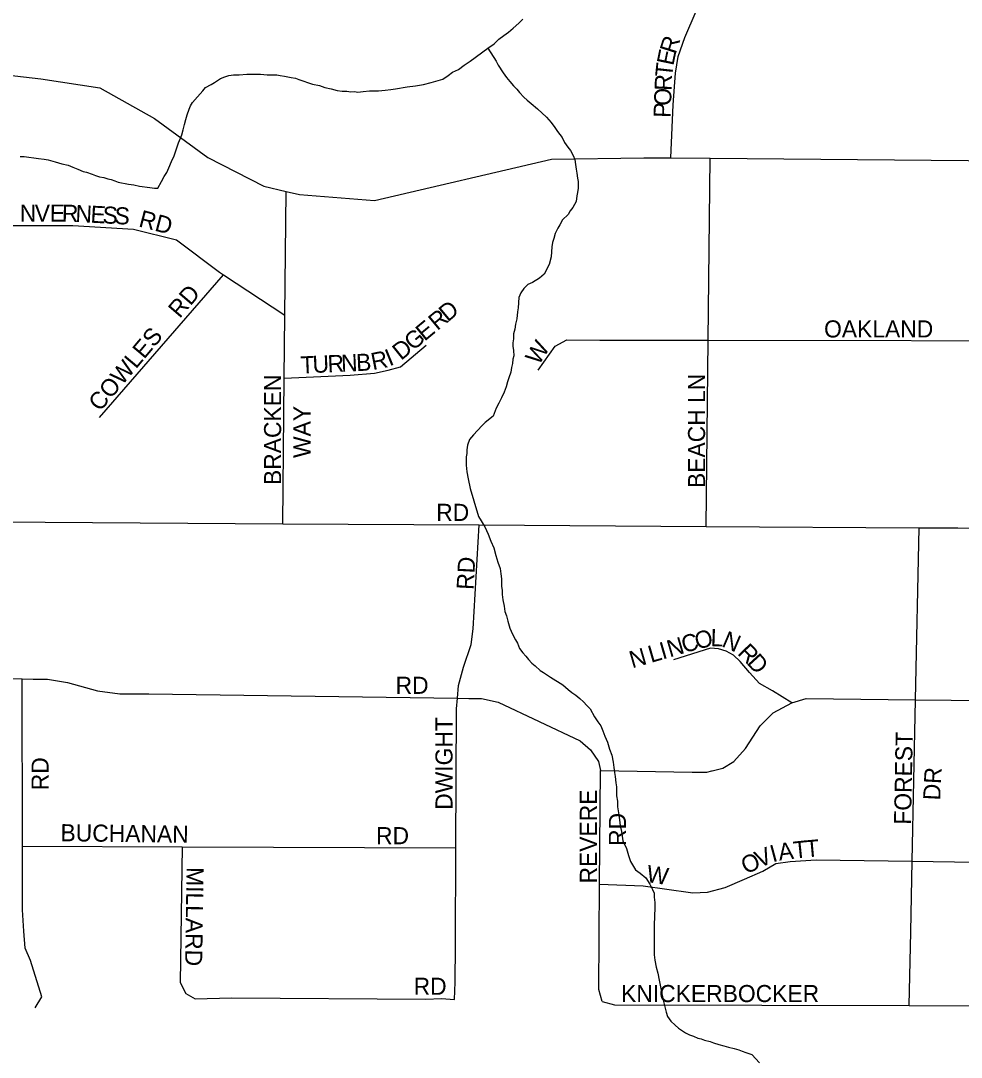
# Model space of a CAD drawing. Extents: x 2010165 to 2382125, y 1060529 to 1407316.
# Drawn here: x 2120912 to 2123664, y 1267507 to 1270540 of the extents above; entities that cross this region are included whole.
import ezdxf

# ---------------------------------------------------------------- set-up
doc = ezdxf.new("R2010")
doc.units = 0
for name, color, linetype in [('GM_X_City_Street', 7, 'Continuous'), ('GM_X_City_Street_Text', 7, 'Continuous'), ('GM_X_Minor_River', 7, 'Continuous')]:
    doc.layers.add(name, color=color, linetype=linetype)

msp = doc.modelspace()

# ---------------------------------------------------------------- linework, layer by layer
at = {"layer": 'GM_X_City_Street'}
for points in [[(2122814.6, 1270138.1), (2122820.9, 1270294), (2122828, 1270386.4), (2122835.6, 1270434.7), (2122855.1, 1270491), (2122888.4, 1270567.6), (2122896.4, 1270585.6)], [(2120792, 1270390.5), (2120970.6, 1270369.4), (2121142.7, 1270343.6), (2121302.8, 1270253.5), (2121459, 1270139.5), (2121623.1, 1270055.5), (2121688.4, 1270040.5), (2121727.2, 1270031.5), (2121947.3, 1270013.7), (2122465.3, 1270134.5), (2122735.5, 1270138.8), (2122814.6, 1270138.1), (2122929, 1270137.2), (2124116, 1270127.1), (2124592.4, 1270123.1), (2125050.4, 1270119.2), (2125261, 1270121.5), (2126064.8, 1270130.3)], [(2122918, 1269060), (2122923.5, 1269604.6), (2122929, 1270137.2)], [(2121678.3, 1269067.8), (2121682.7, 1269493.8), (2121684.6, 1269678.4), (2121688.4, 1270040.5)], [(2120885.5, 1269940.2), (2121063.6, 1269940.1), (2121241.7, 1269929.6), (2121367.3, 1269898.2), (2121493, 1269803.9), (2121504.7, 1269796.2), (2121684.6, 1269678.4)], [(2121142.3, 1269378.3), (2121504.7, 1269796.2)], [(2122425.6, 1269517.6), (2122476, 1269587.6), (2122510.1, 1269605.5), (2122606.2, 1269605.1), (2122923.5, 1269604.6), (2124112.6, 1269602.6), (2124193.7, 1269602.5), (2124576.9, 1269598.8)], [(2121682.7, 1269493.8), (2121875.3, 1269502.6), (2121946.7, 1269508.5), (2121986.7, 1269516.9), (2122022.7, 1269527.3), (2122098.2, 1269590.3)], [(2119222.9, 1269093.1), (2120523.7, 1269077), (2120842.1, 1269073.1), (2121678.3, 1269067.8), (2122253.4, 1269064.2), (2122918, 1269060), (2123540.6, 1269056.1), (2123654.7, 1269055.4), (2124109.1, 1269053.5), (2124157.2, 1269053.3), (2124271.3, 1269056.8), (2124558.8, 1269064.7), (2124589.6, 1269065.5), (2125090.2, 1269085.5), (2125220.4, 1269093), (2125228.4, 1269093), (2125340.5, 1269092.5), (2126423.4, 1269090.4)], [(2122181, 1267676.1), (2122183.2, 1267726.3), (2122183.7, 1267832.5), (2122185, 1268119.2), (2122186.9, 1268526.2), (2122189.8, 1268557.2), (2122193.2, 1268594.3), (2122207.4, 1268648.4), (2122229.8, 1268714.5), (2122236, 1268760.6), (2122253.4, 1269064.2)], [(2123516.6, 1267873.5), (2123520.8, 1268080.5), (2123530.4, 1268552.9), (2123540.6, 1269056.1)], [(2123167.9, 1268544.2), (2123112, 1268578.5), (2123074.1, 1268600.7), (2123044.2, 1268632.9), (2123017.4, 1268665), (2122997.4, 1268683.7), (2122976.4, 1268695.3), (2122954, 1268701.7), (2122930.4, 1268703.6), (2122822.1, 1268669.9)], [(2120669.8, 1268618.7), (2120916.1, 1268614.1), (2120948.1, 1268613.5), (2120990.1, 1268613.4), (2121048.1, 1268603.1), (2121136.1, 1268578.7), (2121201.7, 1268570), (2121286.2, 1268570), (2122189.8, 1268557.2), (2122222.9, 1268556.7), (2122260.4, 1268556.7), (2122309.1, 1268545.8), (2122548.8, 1268432.5), (2122578.7, 1268406.3), (2122602.6, 1268372.1), (2122608.5, 1268346), (2122876.7, 1268340.9), (2122919.2, 1268340.6), (2122933.8, 1268344.3)], [(2120953.7, 1267651.2), (2120973.8, 1267683.2), (2120940.3, 1267789.6), (2120924.4, 1267825.7), (2120920.7, 1267875.9), (2120917, 1267938), (2120916.7, 1268124.4), (2120916.1, 1268614.1)], [(2122933.8, 1268344.3), (2122935.1, 1268344.6), (2122966.8, 1268352.5), (2122999, 1268372.5), (2123033.2, 1268410.4), (2123075.5, 1268476.4), (2123113.7, 1268514.3), (2123167.9, 1268544.2), (2123210, 1268556), (2123530.4, 1268552.9), (2123946.7, 1268549), (2124014.7, 1268548.7), (2124102.8, 1268542.3), (2124477, 1268494.6), (2124515.6, 1268490.9), (2124521.7, 1268490.3)], [(2122613.4, 1267670.3), (2122603.5, 1267704.5), (2122605.9, 1268013.2), (2122608.5, 1268346)], [(2120916.7, 1268124.4), (2121384.2, 1268122.5), (2122185, 1268119.2)], [(2121384.2, 1268122.5), (2121378.4, 1267725.6), (2121394.3, 1267693.4), (2121422.3, 1267677.3), (2121528.4, 1267680.9), (2122096.9, 1267676.5), (2122143, 1267678.3), (2122181, 1267676.1)], [(2122871.5, 1267989.1), (2122879.1, 1267988), (2122921.1, 1267989.9), (2122973.2, 1268003.7), (2123029.4, 1268027.5), (2123083.6, 1268051.3), (2123121.7, 1268073.2), (2123163.8, 1268079.1), (2123239.9, 1268084.8), (2123520.8, 1268080.5), (2124508.7, 1268065.3)], [(2122605.9, 1268013.2), (2122733, 1268008.7), (2122871.5, 1267989.1)], [(2123512.2, 1267658.5), (2123516.6, 1267873.5), (2123516.6, 1267873.5)], [(2122613.4, 1267670.3), (2122649.4, 1267660.2), (2123512.2, 1267658.5), (2124503.2, 1267656.5), (2124717.3, 1267653.6), (2124791.4, 1267651.3), (2124881.4, 1267642.9), (2124967.5, 1267634.5), (2125023.5, 1267632.3), (2125113.6, 1267631.9), (2125178.8, 1267632.5)]]:
    msp.add_lwpolyline(points, dxfattribs=at)
at = {"layer": 'GM_X_Minor_River'}
for points in [[(2122008.4, 1270340.6), (2122020.5, 1270342.6), (2122030.5, 1270344.7), (2122042.5, 1270346.7), (2122066.6, 1270348.8), (2122090.7, 1270352.9), (2122112.7, 1270359), (2122132.8, 1270365.1), (2122146.8, 1270369.1), (2122162.8, 1270379.2), (2122174.8, 1270389.3), (2122192.9, 1270397.3), (2122208.9, 1270409.4), (2122226.9, 1270421.5), (2122278.9, 1270459.8), (2122297, 1270471.9), (2122311, 1270486), (2122325, 1270496.1), (2122339, 1270506.1), (2122353, 1270518.2), (2122369, 1270532.3), (2122381, 1270544.4)], [(2122278.3, 1270459.3), (2122303.1, 1270421.8), (2122309.2, 1270409.8), (2122323.3, 1270387.7), (2122333.4, 1270373.7), (2122343.5, 1270361.7), (2122353.6, 1270349.7), (2122363.6, 1270339.7), (2122371.7, 1270329.7), (2122383.8, 1270315.7), (2122393.8, 1270307.7), (2122405.9, 1270297.7), (2122424, 1270281.7), (2122450.2, 1270257.7), (2122464.3, 1270241.7), (2122474.4, 1270227.7), (2122482.5, 1270215.7), (2122496.6, 1270197.6), (2122502.6, 1270183.6), (2122512.7, 1270169.6), (2122520.8, 1270159.6), (2122528.8, 1270145.6), (2122532.9, 1270133.6), (2122535, 1270119.5), (2122537, 1270105.5), (2122539.1, 1270093.4), (2122541.1, 1270079.4), (2122543.2, 1270069.4), (2122543.2, 1270049.3), (2122541.3, 1270037.3), (2122539.3, 1270027.2), (2122537.3, 1270011.2), (2122527.4, 1269993.1), (2122519.4, 1269983), (2122513.4, 1269973), (2122497.4, 1269956.9), (2122489.4, 1269942.8), (2122483.4, 1269932.7), (2122475.5, 1269916.7), (2122471.5, 1269902.6), (2122467.5, 1269890.6), (2122465.6, 1269878.5), (2122463.7, 1269848.4), (2122457.7, 1269826.3), (2122443.8, 1269798.2), (2122429.8, 1269786.1), (2122409.7, 1269774), (2122395.7, 1269767.9), (2122383.7, 1269755.8), (2122375.7, 1269743.8), (2122369.8, 1269729.7), (2122367.9, 1269699.6), (2122365.9, 1269687.6), (2122364, 1269667.5), (2122360, 1269651.4), (2122358, 1269637.4), (2122354.1, 1269623.3), (2122354.1, 1269609.3), (2122352.1, 1269597.2), (2122352.2, 1269587.2), (2122354.2, 1269575.2), (2122354.3, 1269559.1), (2122352.3, 1269549.1), (2122350.4, 1269537), (2122348.4, 1269525), (2122346.4, 1269510.9), (2122340.5, 1269494.8), (2122336.5, 1269482.8), (2122332.5, 1269468.7), (2122326.6, 1269452.7), (2122318.6, 1269436.6), (2122310.6, 1269420.5), (2122302.6, 1269406.4), (2122294.7, 1269382.3), (2122270.7, 1269364.2), (2122260.7, 1269354.1), (2122236.7, 1269328), (2122224.7, 1269313.9), (2122218.7, 1269297.8), (2122216.8, 1269283.8), (2122216.8, 1269273.7), (2122214.8, 1269263.7), (2122214.9, 1269253.7), (2122214.9, 1269239.6), (2122217, 1269219.6), (2122221.1, 1269199.5), (2122227.2, 1269171.4), (2122237.4, 1269135.3), (2122251.6, 1269089.2), (2122269.7, 1269059.2), (2122279.8, 1269037.2), (2122287.9, 1269017.1), (2122296, 1268997.1), (2122302.1, 1268975), (2122308.2, 1268955), (2122314.3, 1268936.9), (2122316.4, 1268920.9), (2122318.4, 1268906.9), (2122318.5, 1268894.8)], [(2120909.5, 1270142.5), (2120921.5, 1270142.5), (2120935.6, 1270140.6), (2120949.6, 1270138.6), (2120963.7, 1270136.6), (2120979.7, 1270134.7), (2120991.8, 1270132.7), (2121011.9, 1270126.7), (2121032, 1270120.8), (2121050, 1270116.8), (2121064.1, 1270110.9), (2121078.2, 1270104.9), (2121094.2, 1270098.9), (2121104.3, 1270096.9), (2121120.4, 1270091), (2121130.4, 1270087), (2121142.5, 1270083), (2121154.5, 1270081), (2121166.6, 1270077.1), (2121176.6, 1270075.1), (2121186.6, 1270071.1), (2121196.7, 1270067.1), (2121226.8, 1270061.2), (2121242.9, 1270059.3), (2121258.9, 1270055.3), (2121289.1, 1270051.4), (2121303.1, 1270049.4), (2121313.1, 1270049.4), (2121323.1, 1270069.5), (2121331.1, 1270083.6), (2121339.1, 1270095.7), (2121345, 1270109.7), (2121353, 1270127.8), (2121361, 1270143.9), (2121366.9, 1270162), (2121372.9, 1270182.1), (2121378.9, 1270196.1), (2121382.8, 1270206.2), (2121386.8, 1270220.2), (2121390.7, 1270236.3), (2121394.7, 1270250.4), (2121398.7, 1270264.4), (2121404.6, 1270280.5), (2121408.6, 1270290.5), (2121414.6, 1270300.6), (2121428.6, 1270316.7), (2121444.6, 1270334.8), (2121452.6, 1270344.8), (2121468.6, 1270352.9), (2121478.6, 1270359), (2121496.6, 1270371.1), (2121508.7, 1270375.1), (2121520.7, 1270379.2), (2121534.7, 1270381.2), (2121550.8, 1270381.3), (2121572.9, 1270383.3), (2121594.9, 1270383.4), (2121613, 1270383.5), (2121633.1, 1270381.5), (2121649.1, 1270381.6), (2121661.2, 1270381.6), (2121671.2, 1270379.6), (2121683.2, 1270377.7), (2121693.3, 1270375.7), (2121703.3, 1270373.7), (2121715.4, 1270371.8), (2121725.4, 1270367.8), (2121765.6, 1270353.9), (2121785.7, 1270349.9), (2121801.8, 1270343.9), (2121819.8, 1270340), (2121837.9, 1270336), (2121852, 1270334.1), (2121866, 1270334.1), (2121878, 1270332.1), (2121888.1, 1270332.2), (2121898.1, 1270330.2), (2121914.2, 1270332.2), (2121932.2, 1270334.3), (2121958.3, 1270334.4), (2121978.4, 1270336.5), (2121994.4, 1270338.5), (2122008.4, 1270340.6)], [(2122318.5, 1268894.8), (2122318.5, 1268884.8), (2122320.5, 1268872.8), (2122320.6, 1268860.7), (2122322.6, 1268844.7), (2122326.7, 1268826.6), (2122328.8, 1268810.6), (2122332.8, 1268798.6), (2122336.9, 1268782.5), (2122343, 1268762.5), (2122351.1, 1268744.4), (2122359.2, 1268728.4), (2122365.2, 1268718.4), (2122371.3, 1268702.4), (2122381.4, 1268690.3), (2122389.4, 1268680.3), (2122397.5, 1268670.3), (2122407.6, 1268660.3), (2122417.6, 1268652.3), (2122431.7, 1268638.3), (2122441.8, 1268632.3), (2122461.9, 1268618.4), (2122498.1, 1268596.4), (2122514.2, 1268582.4), (2122524.2, 1268574.4), (2122536.3, 1268566.4), (2122548.4, 1268556.4), (2122558.5, 1268546.4), (2122568.5, 1268536.4), (2122578.6, 1268526.4), (2122590.7, 1268502.4), (2122600.8, 1268488.4), (2122608.9, 1268476.4), (2122614.9, 1268462.3), (2122621, 1268446.3), (2122629.1, 1268428.3), (2122635.2, 1268408.2), (2122641.3, 1268390.2), (2122645.4, 1268370.1), (2122647.4, 1268354.1), (2122649.5, 1268340), (2122651.5, 1268328), (2122653.6, 1268310), (2122655.6, 1268297.9), (2122655.7, 1268285.9), (2122655.7, 1268271.8), (2122657.8, 1268255.8), (2122657.8, 1268239.7), (2122659.9, 1268227.7), (2122661.9, 1268215.7), (2122664, 1268201.6), (2122666.1, 1268183.6), (2122670.1, 1268167.5), (2122674.2, 1268139.5), (2122684.4, 1268117.4), (2122690.4, 1268097.4), (2122696.5, 1268079.3), (2122704.6, 1268065.3), (2122710.7, 1268055.3), (2122724.7, 1268045.3), (2122740.8, 1268031.3), (2122752.9, 1268013.3), (2122761, 1267997.3), (2122765.1, 1267987.2), (2122765.1, 1267975.2), (2122767.2, 1267959.2), (2122767.2, 1267945.1), (2122765.4, 1267892.9), (2122765.5, 1267874.9), (2122765.5, 1267852.8), (2122765.6, 1267830.7), (2122765.7, 1267806.7), (2122767.8, 1267790.6), (2122771.8, 1267770.6), (2122775.9, 1267752.5), (2122780, 1267732.5), (2122784.1, 1267712.4), (2122788.2, 1267692.4), (2122792.3, 1267670.3), (2122796.3, 1267654.2), (2122800.4, 1267638.2), (2122804.4, 1267626.2), (2122814.5, 1267612.2), (2122826.6, 1267600.2), (2122836.7, 1267592.2), (2122856.8, 1267578.2), (2122868.8, 1267572.2), (2122880.9, 1267568.2), (2122893, 1267562.3), (2122903, 1267560.3), (2122913, 1267556.3), (2122929.1, 1267552.3), (2122939.2, 1267548.4), (2122955.2, 1267544.4), (2122969.3, 1267540.4), (2122983.3, 1267536.5), (2122999.4, 1267532.5), (2123013.5, 1267528.5), (2123023.5, 1267524.5), (2123033.6, 1267520.6), (2123051.7, 1267514.6)], [(2123051.7, 1267514.6), (2123073.8, 1267490.6)]]:
    msp.add_lwpolyline(points, dxfattribs=at)

# ---------------------------------------------------------------- texts
at = {"layer": 'GM_X_City_Street_Text'}
for s, rotation, p in [('R', 72.4098, (2122828.2, 1270439.7)), ('E', 78.2963, (2122821.4, 1270406.5)), ('T', 83.8272, (2122817.8, 1270372.8)), ('R', 87.8021, (2122816.4, 1270334.1)), ('O', 87.8085, (2122814.7, 1270290.1)), ('P', 87.8142, (2122813.3, 1270255)), ('N', 359.9758, (2120908.7, 1269951.7)), ('V', 359.9758, (2120952.7, 1269951.7)), ('E', 359.9727, (2120996.7, 1269951.7)), ('R', 359.1014, (2121031.7, 1269951.6)), ('N', 357.2233, (2121070.9, 1269951)), ('E', 356.8838, (2121114.8, 1269948.9)), ('S', 356.9172, (2121150, 1269947)), ('S', 356.9111, (2121185.1, 1269945.1)), ('RD', 345.2542, (2121254.3, 1269938.2)), ('RD', 49.4006, (2121376.8, 1269666.8)), ('R', 39.6684, (2122130.8, 1269631.2)), ('D', 39.6792, (2122161.3, 1269656.5)), ('E', 39.6709, (2122093.6, 1269600.3)), ('OAKLAND', 0, (2123262.7, 1269612.9)), ('COWLES', 49.9418, (2121143.5, 1269394)), ('G', 39.6792, (2122059.7, 1269572.3)), ('D', 38.6419, (2122024.6, 1269544.2)), ('W', 57.5237, (2122427.6, 1269529.3)), ('N', 2.4706, (2121850.1, 1269512.5)), ('B', 2.4694, (2121894.1, 1269514.4)), ('R', 11.4382, (2121942.1, 1269517.1)), ('I', 22.1643, (2121990.7, 1269527.9)), ('T', 2.4872, (2121731.4, 1269507.3)), ('U', 2.4706, (2121766.6, 1269508.9)), ('R', 2.4694, (2121810.5, 1269510.8)), ('BRACKEN', 90, (2121673.7, 1269181.1)), ('BEACH LN', 90, (2122914.5, 1269172.3)), ('WAY', 90, (2121759.7, 1269260.3)), ('RD', 0, (2122127.5, 1269076.1)), ('RD', 86.9827, (2122237, 1268873.6)), ('C', 16.2189, (2122853.4, 1268688.7)), ('O', 13.8613, (2122890.9, 1268699.6)), ('L', 358.0599, (2122930, 1268709.8)), ('N', 336.9851, (2122960.5, 1268709.7)), ('I', 16.1736, (2122790, 1268670.3)), ('N', 16.2091, (2122811.2, 1268676.4)), ('R', 314.4934, (2123007.2, 1268687.3)), ('N', 16.1916, (2122701.2, 1268644.5)), ('L', 16.1968, (2122756.2, 1268660.5)), ('D', 312.4567, (2123034.6, 1268659.4)), ('RD', 0, (2122008.7, 1268570.1)), ('DWIGHT', 90, (2122175.3, 1268230.7)), ('FOREST', 88.8989, (2123517.3, 1268186.9)), ('RD', 90, (2120993.2, 1268287.9)), ('DR', 86.9884, (2123602.3, 1268257.5)), ('REVERE', 90, (2122597.8, 1268015.1)), ('RD', 90, (2122682.8, 1268125.1)), ('BUCHANAN', 359.2752, (2121027.7, 1268138.9)), ('RD', 0, (2121951.5, 1268130.1)), ('T', 5.9661, (2123175.1, 1268087.6)), ('T', 5.0881, (2123209.9, 1268091.2)), ('V', 23.6607, (2123073.8, 1268059.7)), ('I', 15.0807, (2123112.3, 1268076.7)), ('A', 7.2985, (2123131.7, 1268082)), ('O', 25.0301, (2123034.2, 1268041.2)), ('MILLARD', 269.0911, (2121397.1, 1268063.4)), ('W', 351.2589, (2122740.6, 1268020)), ('RD', 0, (2122061.5, 1267689.5)), ('KNICKERBOCKER', 0, (2122668.7, 1267668.1))]:
    msp.add_text(s, height=50, rotation=rotation, dxfattribs=at).set_placement(p)

doc.saveas('drawing.dxf')
